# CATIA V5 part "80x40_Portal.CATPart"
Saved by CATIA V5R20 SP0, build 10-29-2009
Part number: 80x40_Portal
Nomenclature: P40x80L_N8_I
Source: Unknown
Bounding box of the stored display mesh (mm): x -25.6 to 54.4, y 0 to 40, z 120 to 1000
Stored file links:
  C:\Users\Andi\Desktop\Plasma\80x40_Portal.CATPart
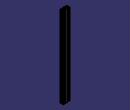
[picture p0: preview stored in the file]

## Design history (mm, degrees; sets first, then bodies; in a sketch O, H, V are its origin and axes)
Set1
  Sketch1 on face of Solid1, origin (0, 0, 0), H (1, 0, 0), V (0, -1, 0)
    projected arc E1 centre (2, -35.5) radius 2.5 from (2, -38) to (4.5, -35.5) ccw from edge [face of Solid1 | face of Solid1]
    projected arc E2 centre (2, -37.5) radius 0.5 from (1.5, -37.5) to (2, -38) ccw from edge [face of Solid1 | face of Solid1]
    projected line E3 (1.5, -35.85) -> (1.5, -37.5) from edge [face of Solid1 | face of Solid1]
    projected arc E4 centre (1, -35.85) radius 0.5 from (1.5, -35.85) to (1, -35.35) ccw from edge [face of Solid1 | face of Solid1]
    projected line E5 (-0.5, -35.35) -> (1, -35.35) from edge [face of Solid1 | face of Solid1]
    projected arc E6 centre (-0.5, -36.35) radius 1 from (-0.5, -35.35) to (-1.5, -36.35) ccw from edge [face of Solid1 | face of Solid1]
    projected line E7 (-1.5, -38.5) -> (-1.5, -36.35) from edge [face of Solid1 | face of Solid1]
    projected arc E8 centre (0, -38.5) radius 1.5 from (-1.5, -38.5) to (0, -40) ccw from edge [face of Solid1 | face of Solid1]
    projected line E9 (28.8, -40) -> (0, -40) from edge [face of Solid1 | face of Solid1]
    projected arc E10 centre (28.8, -38.5) radius 1.5 from (28.8, -40) to (30.3, -38.5) ccw from edge [face of Solid1 | face of Solid1]
    projected line E11 (30.3, -36.35) -> (30.3, -38.5) from edge [face of Solid1 | face of Solid1]
    projected arc E12 centre (29.3, -36.35) radius 1 from (30.3, -36.35) to (29.3, -35.35) ccw from edge [face of Solid1 | face of Solid1]
    projected line E13 (27.8, -35.35) -> (29.3, -35.35) from edge [face of Solid1 | face of Solid1]
    projected arc E14 centre (27.8, -35.85) radius 0.5 from (27.8, -35.35) to (27.3, -35.85) ccw from edge [face of Solid1 | face of Solid1]
    projected line E15 (27.3, -37.5) -> (27.3, -35.85) from edge [face of Solid1 | face of Solid1]
    projected arc E16 centre (26.8, -37.5) radius 0.5 from (26.8, -38) to (27.3, -37.5) ccw from edge [face of Solid1 | face of Solid1]
    projected arc E17 centre (26.8, -35.5) radius 2.5 from (24.3, -35.5) to (26.8, -38) ccw from edge [face of Solid1 | face of Solid1]
    projected line E18 (24.3, -34.2924) -> (24.3, -35.5) from edge [face of Solid1 | face of Solid1]
    projected arc E19 centre (29.3, -34.2924) radius 5 from (25.7645, -30.7569) to (24.3, -34.2924) ccw from edge [face of Solid1 | face of Solid1]
    projected line E20 (27.4569, -29.0645) -> (25.7645, -30.7569) from edge [face of Solid1 | face of Solid1]
    projected arc E21 centre (30.9924, -32.6) radius 5 from (30.9924, -27.6) to (27.4569, -29.0645) ccw from edge [face of Solid1 | face of Solid1]
    projected line E22 (37.8076, -27.6) -> (30.9924, -27.6) from edge [face of Solid1 | face of Solid1]
    projected arc E23 centre (37.8076, -32.6) radius 5 from (41.3431, -29.0645) to (37.8076, -27.6) ccw from edge [face of Solid1 | face of Solid1]
    projected line E24 (43.0355, -30.7569) -> (41.3431, -29.0645) from edge [face of Solid1 | face of Solid1]
    projected arc E25 centre (39.5, -34.2924) radius 5 from (44.5, -34.2924) to (43.0355, -30.7569) ccw from edge [face of Solid1 | face of Solid1]
    projected line E26 (44.5, -35.5) -> (44.5, -34.2924) from edge [face of Solid1 | face of Solid1]
    projected arc E27 centre (42, -35.5) radius 2.5 from (42, -38) to (44.5, -35.5) ccw from edge [face of Solid1 | face of Solid1]
    projected arc E28 centre (42, -37.5) radius 0.5 from (41.5, -37.5) to (42, -38) ccw from edge [face of Solid1 | face of Solid1]
    projected line E29 (41.5, -35.85) -> (41.5, -37.5) from edge [face of Solid1 | face of Solid1]
    projected arc E30 centre (41, -35.85) radius 0.5 from (41.5, -35.85) to (41, -35.35) ccw from edge [face of Solid1 | face of Solid1]
    projected line E31 (39.5, -35.35) -> (41, -35.35) from edge [face of Solid1 | face of Solid1]
    projected arc E32 centre (39.5, -36.35) radius 1 from (39.5, -35.35) to (38.5, -36.35) ccw from edge [face of Solid1 | face of Solid1]
    projected line E33 (38.5, -38.5) -> (38.5, -36.35) from edge [face of Solid1 | face of Solid1]
    projected arc E34 centre (40, -38.5) radius 1.5 from (38.5, -38.5) to (40, -40) ccw from edge [face of Solid1 | face of Solid1]
    projected line E35 (50.4, -40) -> (40, -40) from edge [face of Solid1 | face of Solid1]
    projected arc E36 centre (50.4, -36) radius 4 from (50.4, -40) to (54.4, -36) ccw from edge [face of Solid1 | face of Solid1]
    projected line E37 (54.4, -25.6) -> (54.4, -36) from edge [face of Solid1 | face of Solid1]
    projected arc E38 centre (52.9, -25.6) radius 1.5 from (54.4, -25.6) to (52.9, -24.1) ccw from edge [face of Solid1 | face of Solid1]
    projected line E39 (50.75, -24.1) -> (52.9, -24.1) from edge [face of Solid1 | face of Solid1]
    projected arc E40 centre (50.75, -25.1) radius 1 from (50.75, -24.1) to (49.75, -25.1) ccw from edge [face of Solid1 | face of Solid1]
    projected line E41 (49.75, -26.6) -> (49.75, -25.1) from edge [face of Solid1 | face of Solid1]
    projected arc E42 centre (50.25, -26.6) radius 0.5 from (49.75, -26.6) to (50.25, -27.1) ccw from edge [face of Solid1 | face of Solid1]
    projected line E43 (51.9, -27.1) -> (50.25, -27.1) from edge [face of Solid1 | face of Solid1]
    projected arc E44 centre (51.9, -27.6) radius 0.5 from (52.4, -27.6) to (51.9, -27.1) ccw from edge [face of Solid1 | face of Solid1]
    projected arc E45 centre (49.9, -27.6) radius 2.5 from (49.9, -30.1) to (52.4, -27.6) ccw from edge [face of Solid1 | face of Solid1]
    projected line E46 (48.6924, -30.1) -> (49.9, -30.1) from edge [face of Solid1 | face of Solid1]
    projected arc E47 centre (48.6924, -25.1) radius 5 from (45.1569, -28.6355) to (48.6924, -30.1) ccw from edge [face of Solid1 | face of Solid1]
    projected line E48 (43.4645, -26.9431) -> (45.1569, -28.6355) from edge [face of Solid1 | face of Solid1]
    projected arc E49 centre (47, -23.4076) radius 5 from (42, -23.4076) to (43.4645, -26.9431) ccw from edge [face of Solid1 | face of Solid1]
    projected line E50 (42, -16.5924) -> (42, -23.4076) from edge [face of Solid1 | face of Solid1]
    projected arc E51 centre (47, -16.5924) radius 5 from (43.4645, -13.0569) to (42, -16.5924) ccw from edge [face of Solid1 | face of Solid1]
    projected line E52 (45.1569, -11.3645) -> (43.4645, -13.0569) from edge [face of Solid1 | face of Solid1]
    projected arc E53 centre (48.6924, -14.9) radius 5 from (48.6924, -9.9) to (45.1569, -11.3645) ccw from edge [face of Solid1 | face of Solid1]
    projected line E54 (49.9, -9.9) -> (48.6924, -9.9) from edge [face of Solid1 | face of Solid1]
    projected arc E55 centre (49.9, -12.4) radius 2.5 from (52.4, -12.4) to (49.9, -9.9) ccw from edge [face of Solid1 | face of Solid1]
    projected arc E56 centre (51.9, -12.4) radius 0.5 from (51.9, -12.9) to (52.4, -12.4) ccw from edge [face of Solid1 | face of Solid1]
    projected line E57 (50.25, -12.9) -> (51.9, -12.9) from edge [face of Solid1 | face of Solid1]
    projected arc E58 centre (50.25, -13.4) radius 0.5 from (50.25, -12.9) to (49.75, -13.4) ccw from edge [face of Solid1 | face of Solid1]
    projected line E59 (49.75, -14.9) -> (49.75, -13.4) from edge [face of Solid1 | face of Solid1]
    projected arc E60 centre (50.75, -14.9) radius 1 from (49.75, -14.9) to (50.75, -15.9) ccw from edge [face of Solid1 | face of Solid1]
    projected line E61 (52.9, -15.9) -> (50.75, -15.9) from edge [face of Solid1 | face of Solid1]
    projected arc E62 centre (52.9, -14.4) radius 1.5 from (52.9, -15.9) to (54.4, -14.4) ccw from edge [face of Solid1 | face of Solid1]
    projected line E63 (54.4, -4) -> (54.4, -14.4) from edge [face of Solid1 | face of Solid1]
    projected arc E64 centre (50.4, -4) radius 4 from (54.4, -4) to (50.4, 0) ccw from edge [face of Solid1 | face of Solid1]
    projected line E65 (40, 0) -> (50.4, 0) from edge [face of Solid1 | face of Solid1]
    projected arc E66 centre (40, -1.5) radius 1.5 from (40, 0) to (38.5, -1.5) ccw from edge [face of Solid1 | face of Solid1]
    projected line E67 (38.5, -3.65) -> (38.5, -1.5) from edge [face of Solid1 | face of Solid1]
    projected arc E68 centre (39.5, -3.65) radius 1 from (38.5, -3.65) to (39.5, -4.65) ccw from edge [face of Solid1 | face of Solid1]
    projected line E69 (41, -4.65) -> (39.5, -4.65) from edge [face of Solid1 | face of Solid1]
    projected arc E70 centre (41, -4.15) radius 0.5 from (41, -4.65) to (41.5, -4.15) ccw from edge [face of Solid1 | face of Solid1]
    projected line E71 (41.5, -2.5) -> (41.5, -4.15) from edge [face of Solid1 | face of Solid1]
    projected arc E72 centre (42, -2.5) radius 0.5 from (42, -2) to (41.5, -2.5) ccw from edge [face of Solid1 | face of Solid1]
    projected arc E73 centre (42, -4.5) radius 2.5 from (44.5, -4.5) to (42, -2) ccw from edge [face of Solid1 | face of Solid1]
    projected line E74 (44.5, -5.7076) -> (44.5, -4.5) from edge [face of Solid1 | face of Solid1]
    projected arc E75 centre (39.5, -5.7076) radius 5 from (43.0355, -9.2431) to (44.5, -5.7076) ccw from edge [face of Solid1 | face of Solid1]
    projected line E76 (41.3431, -10.9355) -> (43.0355, -9.2431) from edge [face of Solid1 | face of Solid1]
    projected arc E77 centre (37.8076, -7.4) radius 5 from (37.8076, -12.4) to (41.3431, -10.9355) ccw from edge [face of Solid1 | face of Solid1]
    projected line E78 (30.9924, -12.4) -> (37.8076, -12.4) from edge [face of Solid1 | face of Solid1]
    projected arc E79 centre (30.9924, -7.4) radius 5 from (27.4569, -10.9355) to (30.9924, -12.4) ccw from edge [face of Solid1 | face of Solid1]
    projected line E80 (25.7645, -9.2431) -> (27.4569, -10.9355) from edge [face of Solid1 | face of Solid1]
    projected arc E81 centre (29.3, -5.7076) radius 5 from (24.3, -5.7076) to (25.7645, -9.2431) ccw from edge [face of Solid1 | face of Solid1]
    projected line E82 (24.3, -4.5) -> (24.3, -5.7076) from edge [face of Solid1 | face of Solid1]
    projected arc E83 centre (26.8, -4.5) radius 2.5 from (26.8, -2) to (24.3, -4.5) ccw from edge [face of Solid1 | face of Solid1]
    projected arc E84 centre (26.8, -2.5) radius 0.5 from (27.3, -2.5) to (26.8, -2) ccw from edge [face of Solid1 | face of Solid1]
    projected line E85 (27.3, -4.15) -> (27.3, -2.5) from edge [face of Solid1 | face of Solid1]
    projected arc E86 centre (27.8, -4.15) radius 0.5 from (27.3, -4.15) to (27.8, -4.65) ccw from edge [face of Solid1 | face of Solid1]
    projected line E87 (29.3, -4.65) -> (27.8, -4.65) from edge [face of Solid1 | face of Solid1]
    projected arc E88 centre (29.3, -3.65) radius 1 from (29.3, -4.65) to (30.3, -3.65) ccw from edge [face of Solid1 | face of Solid1]
    projected line E89 (30.3, -1.5) -> (30.3, -3.65) from edge [face of Solid1 | face of Solid1]
    projected arc E90 centre (28.8, -1.5) radius 1.5 from (30.3, -1.5) to (28.8, 0) ccw from edge [face of Solid1 | face of Solid1]
    projected line E91 (0, 0) -> (28.8, 0) from edge [face of Solid1 | face of Solid1]
    projected arc E92 centre (0, -1.5) radius 1.5 from (0, 0) to (-1.5, -1.5) ccw from edge [face of Solid1 | face of Solid1]
    projected line E93 (-1.5, -3.65) -> (-1.5, -1.5) from edge [face of Solid1 | face of Solid1]
    projected arc E94 centre (-0.5, -3.65) radius 1 from (-1.5, -3.65) to (-0.5, -4.65) ccw from edge [face of Solid1 | face of Solid1]
    projected line E95 (1, -4.65) -> (-0.5, -4.65) from edge [face of Solid1 | face of Solid1]
    projected arc E96 centre (1, -4.15) radius 0.5 from (1, -4.65) to (1.5, -4.15) ccw from edge [face of Solid1 | face of Solid1]
    projected line E97 (1.5, -2.5) -> (1.5, -4.15) from edge [face of Solid1 | face of Solid1]
    projected arc E98 centre (2, -2.5) radius 0.5 from (2, -2) to (1.5, -2.5) ccw from edge [face of Solid1 | face of Solid1]
    projected arc E99 centre (2, -4.5) radius 2.5 from (4.5, -4.5) to (2, -2) ccw from edge [face of Solid1 | face of Solid1]
    projected line E100 (4.5, -5.7076) -> (4.5, -4.5) from edge [face of Solid1 | face of Solid1]
    projected arc E101 centre (-0.5, -5.7076) radius 5 from (3.0355, -9.2431) to (4.5, -5.7076) ccw from edge [face of Solid1 | face of Solid1]
    projected line E102 (1.3431, -10.9355) -> (3.0355, -9.2431) from edge [face of Solid1 | face of Solid1]
    projected arc E103 centre (-2.1924, -7.4) radius 5 from (-2.1924, -12.4) to (1.3431, -10.9355) ccw from edge [face of Solid1 | face of Solid1]
    projected line E104 (-9.0076, -12.4) -> (-2.1924, -12.4) from edge [face of Solid1 | face of Solid1]
    projected arc E105 centre (-9.0076, -7.4) radius 5 from (-12.5431, -10.9355) to (-9.0076, -12.4) ccw from edge [face of Solid1 | face of Solid1]
    projected line E106 (-14.2355, -9.2431) -> (-12.5431, -10.9355) from edge [face of Solid1 | face of Solid1]
    projected arc E107 centre (-10.7, -5.7076) radius 5 from (-15.7, -5.7076) to (-14.2355, -9.2431) ccw from edge [face of Solid1 | face of Solid1]
    projected line E108 (-15.7, -4.5) -> (-15.7, -5.7076) from edge [face of Solid1 | face of Solid1]
    projected arc E109 centre (-13.2, -4.5) radius 2.5 from (-13.2, -2) to (-15.7, -4.5) ccw from edge [face of Solid1 | face of Solid1]
    projected arc E110 centre (-13.2, -2.5) radius 0.5 from (-12.7, -2.5) to (-13.2, -2) ccw from edge [face of Solid1 | face of Solid1]
    projected line E111 (-12.7, -4.15) -> (-12.7, -2.5) from edge [face of Solid1 | face of Solid1]
    projected arc E112 centre (-12.2, -4.15) radius 0.5 from (-12.7, -4.15) to (-12.2, -4.65) ccw from edge [face of Solid1 | face of Solid1]
    projected line E113 (-10.7, -4.65) -> (-12.2, -4.65) from edge [face of Solid1 | face of Solid1]
    projected arc E114 centre (-10.7, -3.65) radius 1 from (-10.7, -4.65) to (-9.7, -3.65) ccw from edge [face of Solid1 | face of Solid1]
    projected line E115 (-9.7, -1.5) -> (-9.7, -3.65) from edge [face of Solid1 | face of Solid1]
    projected arc E116 centre (-11.2, -1.5) radius 1.5 from (-9.7, -1.5) to (-11.2, 0) ccw from edge [face of Solid1 | face of Solid1]
    projected line E117 (-21.6, 0) -> (-11.2, 0) from edge [face of Solid1 | face of Solid1]
    projected arc E118 centre (-21.6, -4) radius 4 from (-21.6, 0) to (-25.6, -4) ccw from edge [face of Solid1 | face of Solid1]
    projected line E119 (-25.6, -14.4) -> (-25.6, -4) from edge [face of Solid1 | face of Solid1]
    projected arc E120 centre (-24.1, -14.4) radius 1.5 from (-25.6, -14.4) to (-24.1, -15.9) ccw from edge [face of Solid1 | face of Solid1]
    projected line E121 (-21.95, -15.9) -> (-24.1, -15.9) from edge [face of Solid1 | face of Solid1]
    projected arc E122 centre (-21.95, -14.9) radius 1 from (-21.95, -15.9) to (-20.95, -14.9) ccw from edge [face of Solid1 | face of Solid1]
    projected line E123 (-20.95, -13.4) -> (-20.95, -14.9) from edge [face of Solid1 | face of Solid1]
    projected arc E124 centre (-21.45, -13.4) radius 0.5 from (-20.95, -13.4) to (-21.45, -12.9) ccw from edge [face of Solid1 | face of Solid1]
    projected line E125 (-23.1, -12.9) -> (-21.45, -12.9) from edge [face of Solid1 | face of Solid1]
    projected arc E126 centre (-23.1, -12.4) radius 0.5 from (-23.6, -12.4) to (-23.1, -12.9) ccw from edge [face of Solid1 | face of Solid1]
    projected arc E127 centre (-21.1, -12.4) radius 2.5 from (-21.1, -9.9) to (-23.6, -12.4) ccw from edge [face of Solid1 | face of Solid1]
    projected line E128 (-19.8924, -9.9) -> (-21.1, -9.9) from edge [face of Solid1 | face of Solid1]
    projected arc E129 centre (-19.8924, -14.9) radius 5 from (-16.3569, -11.3645) to (-19.8924, -9.9) ccw from edge [face of Solid1 | face of Solid1]
    projected line E130 (-14.6645, -13.0569) -> (-16.3569, -11.3645) from edge [face of Solid1 | face of Solid1]
    projected arc E131 centre (-18.2, -16.5924) radius 5 from (-13.2, -16.5924) to (-14.6645, -13.0569) ccw from edge [face of Solid1 | face of Solid1]
    projected line E132 (-13.2, -23.4076) -> (-13.2, -16.5924) from edge [face of Solid1 | face of Solid1]
    projected arc E133 centre (-18.2, -23.4076) radius 5 from (-14.6645, -26.9431) to (-13.2, -23.4076) ccw from edge [face of Solid1 | face of Solid1]
    projected line E134 (-16.3569, -28.6355) -> (-14.6645, -26.9431) from edge [face of Solid1 | face of Solid1]
    projected arc E135 centre (-19.8924, -25.1) radius 5 from (-19.8924, -30.1) to (-16.3569, -28.6355) ccw from edge [face of Solid1 | face of Solid1]
    projected line E136 (-21.1, -30.1) -> (-19.8924, -30.1) from edge [face of Solid1 | face of Solid1]
    projected arc E137 centre (-21.1, -27.6) radius 2.5 from (-23.6, -27.6) to (-21.1, -30.1) ccw from edge [face of Solid1 | face of Solid1]
    projected arc E138 centre (-23.1, -27.6) radius 0.5 from (-23.1, -27.1) to (-23.6, -27.6) ccw from edge [face of Solid1 | face of Solid1]
    projected line E139 (-21.45, -27.1) -> (-23.1, -27.1) from edge [face of Solid1 | face of Solid1]
    projected arc E140 centre (-21.45, -26.6) radius 0.5 from (-21.45, -27.1) to (-20.95, -26.6) ccw from edge [face of Solid1 | face of Solid1]
    projected line E141 (-20.95, -25.1) -> (-20.95, -26.6) from edge [face of Solid1 | face of Solid1]
    projected arc E142 centre (-21.95, -25.1) radius 1 from (-20.95, -25.1) to (-21.95, -24.1) ccw from edge [face of Solid1 | face of Solid1]
    projected line E143 (-24.1, -24.1) -> (-21.95, -24.1) from edge [face of Solid1 | face of Solid1]
    projected arc E144 centre (-24.1, -25.6) radius 1.5 from (-24.1, -24.1) to (-25.6, -25.6) ccw from edge [face of Solid1 | face of Solid1]
    projected line E145 (-25.6, -36) -> (-25.6, -25.6) from edge [face of Solid1 | face of Solid1]
    projected arc E146 centre (-21.6, -36) radius 4 from (-25.6, -36) to (-21.6, -40) ccw from edge [face of Solid1 | face of Solid1]
    projected line E147 (-11.2, -40) -> (-21.6, -40) from edge [face of Solid1 | face of Solid1]
    projected arc E148 centre (-11.2, -38.5) radius 1.5 from (-11.2, -40) to (-9.7, -38.5) ccw from edge [face of Solid1 | face of Solid1]
    projected line E149 (-9.7, -36.35) -> (-9.7, -38.5) from edge [face of Solid1 | face of Solid1]
    projected arc E150 centre (-10.7, -36.35) radius 1 from (-9.7, -36.35) to (-10.7, -35.35) ccw from edge [face of Solid1 | face of Solid1]
    projected line E151 (-12.2, -35.35) -> (-10.7, -35.35) from edge [face of Solid1 | face of Solid1]
    projected arc E152 centre (-12.2, -35.85) radius 0.5 from (-12.2, -35.35) to (-12.7, -35.85) ccw from edge [face of Solid1 | face of Solid1]
    projected line E153 (-12.7, -37.5) -> (-12.7, -35.85) from edge [face of Solid1 | face of Solid1]
    projected arc E154 centre (-13.2, -37.5) radius 0.5 from (-13.2, -38) to (-12.7, -37.5) ccw from edge [face of Solid1 | face of Solid1]
    projected arc E155 centre (-13.2, -35.5) radius 2.5 from (-15.7, -35.5) to (-13.2, -38) ccw from edge [face of Solid1 | face of Solid1]
    projected line E156 (-15.7, -34.2924) -> (-15.7, -35.5) from edge [face of Solid1 | face of Solid1]
    projected arc E157 centre (-10.7, -34.2924) radius 5 from (-14.2355, -30.7569) to (-15.7, -34.2924) ccw from edge [face of Solid1 | face of Solid1]
    projected line E158 (-12.5431, -29.0645) -> (-14.2355, -30.7569) from edge [face of Solid1 | face of Solid1]
    projected arc E159 centre (-9.0076, -32.6) radius 5 from (-9.0076, -27.6) to (-12.5431, -29.0645) ccw from edge [face of Solid1 | face of Solid1]
    projected line E160 (-2.1924, -27.6) -> (-9.0076, -27.6) from edge [face of Solid1 | face of Solid1]
    projected arc E161 centre (-2.1924, -32.6) radius 5 from (1.3431, -29.0645) to (-2.1924, -27.6) ccw from edge [face of Solid1 | face of Solid1]
    projected line E162 (3.0355, -30.7569) -> (1.3431, -29.0645) from edge [face of Solid1 | face of Solid1]
    projected arc E163 centre (-0.5, -34.2924) radius 5 from (4.5, -34.2924) to (3.0355, -30.7569) ccw from edge [face of Solid1 | face of Solid1]
    projected line E164 (4.5, -35.5) -> (4.5, -34.2924) from edge [face of Solid1 | face of Solid1]
    projected arc E165 centre (1.2, -8.2503) radius 5 from (4.7355, -11.7858) to (6.2, -8.2503) ccw from edge [face of Solid1 | face of Solid1]
    projected line E166 (6.2, -8.2503) -> (6.2, -4.5) from edge [face of Solid1 | face of Solid1]
    projected arc E167 centre (8.7, -4.5) radius 2.5 from (8.7, -2) to (6.2, -4.5) ccw from edge [face of Solid1 | face of Solid1]
    projected line E168 (8.7, -2) -> (20.1, -2) from edge [face of Solid1 | face of Solid1]
    projected arc E169 centre (20.1, -4.5) radius 2.5 from (22.6, -4.5) to (20.1, -2) ccw from edge [face of Solid1 | face of Solid1]
    projected line E170 (22.6, -4.5) -> (22.6, -8.2503) from edge [face of Solid1 | face of Solid1]
    projected arc E171 centre (27.6, -8.2503) radius 5 from (22.6, -8.2503) to (24.0645, -11.7858) ccw from edge [face of Solid1 | face of Solid1]
    projected line E172 (24.0645, -11.7858) -> (25.1855, -12.9069) from edge [face of Solid1 | face of Solid1]
    projected arc E173 centre (21.65, -16.4424) radius 5 from (26.65, -16.4424) to (25.1855, -12.9069) ccw from edge [face of Solid1 | face of Solid1]
    projected line E174 (26.65, -16.4424) -> (26.65, -23.5576) from edge [face of Solid1 | face of Solid1]
    projected arc E175 centre (21.65, -23.5576) radius 5 from (25.1855, -27.0931) to (26.65, -23.5576) ccw from edge [face of Solid1 | face of Solid1]
    projected line E176 (25.1855, -27.0931) -> (24.0645, -28.2142) from edge [face of Solid1 | face of Solid1]
    projected arc E177 centre (27.6, -31.7497) radius 5 from (24.0645, -28.2142) to (22.6, -31.7497) ccw from edge [face of Solid1 | face of Solid1]
    projected line E178 (22.6, -31.7497) -> (22.6, -35.5) from edge [face of Solid1 | face of Solid1]
    projected arc E179 centre (20.1, -35.5) radius 2.5 from (20.1, -38) to (22.6, -35.5) ccw from edge [face of Solid1 | face of Solid1]
    projected line E180 (20.1, -38) -> (8.7, -38) from edge [face of Solid1 | face of Solid1]
    projected arc E181 centre (8.7, -35.5) radius 2.5 from (6.2, -35.5) to (8.7, -38) ccw from edge [face of Solid1 | face of Solid1]
    projected line E182 (6.2, -35.5) -> (6.2, -31.7497) from edge [face of Solid1 | face of Solid1]
    projected arc E183 centre (1.2, -31.7497) radius 5 from (6.2, -31.7497) to (4.7355, -28.2142) ccw from edge [face of Solid1 | face of Solid1]
    projected line E184 (4.7355, -28.2142) -> (3.6145, -27.0931) from edge [face of Solid1 | face of Solid1]
    projected arc E185 centre (7.15, -23.5576) radius 5 from (2.15, -23.5576) to (3.6145, -27.0931) ccw from edge [face of Solid1 | face of Solid1]
    projected line E186 (2.15, -23.5576) -> (2.15, -16.4424) from edge [face of Solid1 | face of Solid1]
    projected arc E187 centre (7.15, -16.4424) radius 5 from (3.6145, -12.9069) to (2.15, -16.4424) ccw from edge [face of Solid1 | face of Solid1]
    projected line E188 (3.6145, -12.9069) -> (4.7355, -11.7858) from edge [face of Solid1 | face of Solid1]
    projected arc E189 centre (-23.3, -7.7) radius 0.5 from (-23.8, -7.7) to (-23.3, -8.2) ccw from edge [face of Solid1 | face of Solid1]
    projected line E190 (-23.8, -7.7) -> (-23.8, -4) from edge [face of Solid1 | face of Solid1]
    projected arc E191 centre (-21.6, -4) radius 2.2 from (-21.6, -1.8) to (-23.8, -4) ccw from edge [face of Solid1 | face of Solid1]
    projected line E192 (-21.6, -1.8) -> (-17.9, -1.8) from edge [face of Solid1 | face of Solid1]
    projected arc E193 centre (-17.9, -2.3) radius 0.5 from (-17.4, -2.3) to (-17.9, -1.8) ccw from edge [face of Solid1 | face of Solid1]
    projected line E194 (-17.4, -2.3) -> (-17.4, -7.7) from edge [face of Solid1 | face of Solid1]
    projected arc E195 centre (-17.9, -7.7) radius 0.5 from (-17.9, -8.2) to (-17.4, -7.7) ccw from edge [face of Solid1 | face of Solid1]
    projected line E196 (-17.9, -8.2) -> (-23.3, -8.2) from edge [face of Solid1 | face of Solid1]
    projected arc E197 centre (-17.9, -37.7) radius 0.5 from (-17.9, -38.2) to (-17.4, -37.7) ccw from edge [face of Solid1 | face of Solid1]
    projected line E198 (-17.9, -38.2) -> (-21.6, -38.2) from edge [face of Solid1 | face of Solid1]
    projected arc E199 centre (-21.6, -36) radius 2.2 from (-23.8, -36) to (-21.6, -38.2) ccw from edge [face of Solid1 | face of Solid1]
    projected line E200 (-23.8, -36) -> (-23.8, -32.3) from edge [face of Solid1 | face of Solid1]
    projected arc E201 centre (-23.3, -32.3) radius 0.5 from (-23.3, -31.8) to (-23.8, -32.3) ccw from edge [face of Solid1 | face of Solid1]
    projected line E202 (-23.3, -31.8) -> (-17.9, -31.8) from edge [face of Solid1 | face of Solid1]
    projected arc E203 centre (-17.9, -32.3) radius 0.5 from (-17.4, -32.3) to (-17.9, -31.8) ccw from edge [face of Solid1 | face of Solid1]
    projected line E204 (-17.4, -32.3) -> (-17.4, -37.7) from edge [face of Solid1 | face of Solid1]
    projected arc E205 centre (52.1, -7.7) radius 0.5 from (52.1, -8.2) to (52.6, -7.7) ccw from edge [face of Solid1 | face of Solid1]
    projected line E206 (52.1, -8.2) -> (46.7, -8.2) from edge [face of Solid1 | face of Solid1]
    projected arc E207 centre (46.7, -7.7) radius 0.5 from (46.2, -7.7) to (46.7, -8.2) ccw from edge [face of Solid1 | face of Solid1]
    projected line E208 (46.2, -7.7) -> (46.2, -2.3) from edge [face of Solid1 | face of Solid1]
    projected arc E209 centre (46.7, -2.3) radius 0.5 from (46.7, -1.8) to (46.2, -2.3) ccw from edge [face of Solid1 | face of Solid1]
    projected line E210 (46.7, -1.8) -> (50.4, -1.8) from edge [face of Solid1 | face of Solid1]
    projected arc E211 centre (50.4, -4) radius 2.2 from (52.6, -4) to (50.4, -1.8) ccw from edge [face of Solid1 | face of Solid1]
    projected line E212 (52.6, -4) -> (52.6, -7.7) from edge [face of Solid1 | face of Solid1]
    projected arc E213 centre (46.7, -37.7) radius 0.5 from (46.2, -37.7) to (46.7, -38.2) ccw from edge [face of Solid1 | face of Solid1]
    projected line E214 (46.2, -37.7) -> (46.2, -32.3) from edge [face of Solid1 | face of Solid1]
    projected arc E215 centre (46.7, -32.3) radius 0.5 from (46.7, -31.8) to (46.2, -32.3) ccw from edge [face of Solid1 | face of Solid1]
    projected line E216 (46.7, -31.8) -> (52.1, -31.8) from edge [face of Solid1 | face of Solid1]
    projected arc E217 centre (52.1, -32.3) radius 0.5 from (52.6, -32.3) to (52.1, -31.8) ccw from edge [face of Solid1 | face of Solid1]
    projected line E218 (52.6, -32.3) -> (52.6, -36) from edge [face of Solid1 | face of Solid1]
    projected arc E219 centre (50.4, -36) radius 2.2 from (50.4, -38.2) to (52.6, -36) ccw from edge [face of Solid1 | face of Solid1]
    projected line E220 (50.4, -38.2) -> (46.7, -38.2) from edge [face of Solid1 | face of Solid1]
    projected arc E221 centre (34.4, -20) radius 3.35 from (31.05, -20) to (37.75, -20) ccw from edge [face of Solid1 | face of Solid1]
    projected arc E222 centre (34.4, -20) radius 3.35 from (37.75, -20) to (31.05, -20) ccw from edge [face of Solid1 | face of Solid1]
    projected arc E223 centre (-5.6, -20) radius 3.35 from (-8.95, -20) to (-2.25, -20) ccw from edge [face of Solid1 | face of Solid1]
    projected arc E224 centre (-5.6, -20) radius 3.35 from (-2.25, -20) to (-8.95, -20) ccw from edge [face of Solid1 | face of Solid1]
Body1 "MANIFOLD_SOLID_BREP #7665" (main body)
  Solid1: solid without history
  Pocket1: profile Sketch1, direction (0, 0, 1), length 120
